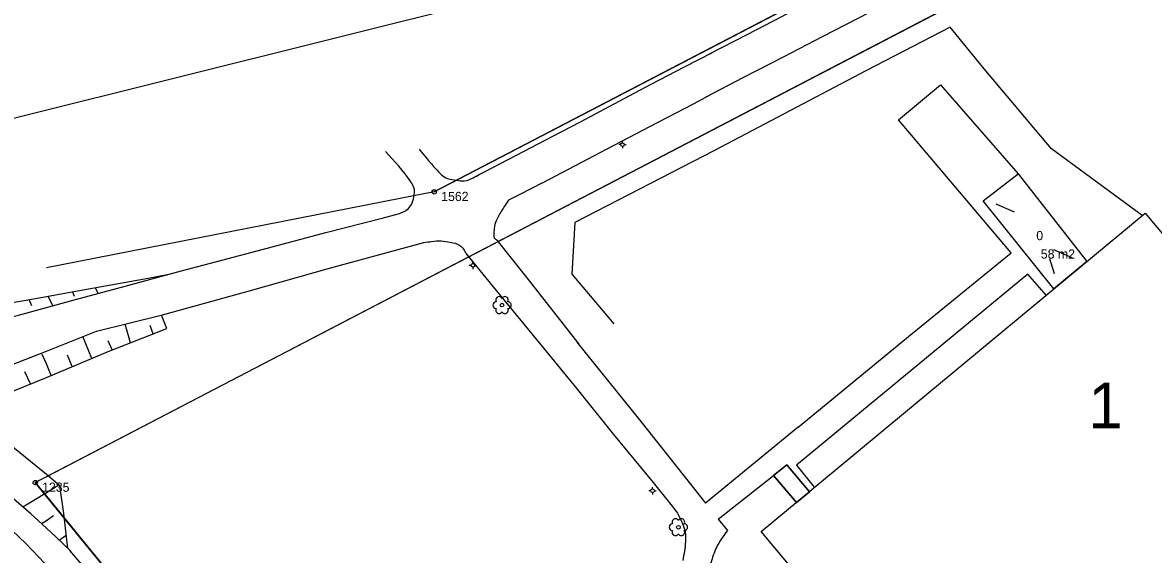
# Model space of a CAD drawing. Extents: x 1517478 to 1518189, y 6494860 to 6495389.
# Drawn here: x 1517715.6 to 1517838.6, y 6495049.6 to 6495107.4 of the extents above; entities that cross this region are included whole.
import ezdxf

# ---------------------------------------------------------------- set-up
doc = ezdxf.new("R2010")
doc.units = 0
for name, color, linetype in [('allmanbygg_symbollinje', 7, 'Continuous'), ('allmanbyggnad', 7, 'Continuous'), ('allmanbyggnad_nummer', 7, 'Continuous'), ('byggnad_areatext', 7, 'Continuous'), ('fastighetsbeteckning', 7, 'Continuous'), ('gc_vag', 7, 'Continuous'), ('grans', 7, 'Continuous'), ('granspunkt', 7, 'Continuous'), ('granspunkt_text', 7, 'Continuous'), ('kvartersgrans', 7, 'Continuous'), ('kvartersytor', 7, 'Continuous'), ('ledningar', 7, 'Continuous'), ('lovtrad', 7, 'Continuous'), ('slant_skraffering', 7, 'Continuous'), ('slantfot', 7, 'Continuous'), ('slantkron', 7, 'Continuous'), ('staket', 7, 'Continuous'), ('stolpe_belysning', 7, 'Continuous'), ('uthus', 7, 'Continuous'), ('uthus_yta', 7, 'Continuous')]:
    doc.layers.add(name, color=color, linetype=linetype)

msp = doc.modelspace()

# ---------------------------------------------------------------- linework, layer by layer
at = {"layer": 'allmanbygg_symbollinje'}
for p, q in [((1517821.5, 6495087.7), (1517823.5, 6495086.83)), ((1517827.76, 6495082.74), (1517829.76, 6495081.87)), ((1517827.33, 6495081.78), (1517827.85, 6495080.13))]:
    msp.add_line(p, q, dxfattribs=at)
at = {"layer": 'allmanbyggnad'}
for points in [[(1517827.79, 6495078.45), (1517820.11, 6495088.05), (1517823.93, 6495091), (1517831.39, 6495081.44), (1517827.79, 6495078.45)], [(1517795.98, 6495052.03), (1517837.72, 6495086.69), (1517844.24, 6495078.9), (1517844.89, 6495079.4), (1517856.96, 6495064.93), (1517856.28, 6495064.33), (1517862.19, 6495057.11), (1517842.98, 6495041.23), (1517844.57, 6495039.29), (1517839.38, 6495035.07), (1517847.33, 6495025.71), (1517853.22, 6495030.6), (1517862.35, 6495019.75), (1517850.98, 6495010.13), (1517853.38, 6495007.24), (1517840.06, 6494996.19), (1517822.37, 6495017.44), (1517823.84, 6495018.69), (1517795.97, 6495052.03)]]:
    msp.add_lwpolyline(points, dxfattribs=at)
at = {"layer": 'gc_vag'}
for p, q in [((1517799.97, 6495063.4), (1517789.92, 6495055.14)), ((1517791.3, 6495053.39), (1517797.31, 6495058.14))]:
    msp.add_line(p, q, dxfattribs=at)
for points in [[(1517790.33, 6495104.03), (1517794.43, 6495106.16), (1517798.2, 6495108.12), (1517802.73, 6495110.59), (1517806.54, 6495112.54), (1517810.49, 6495114.65), (1517815.16, 6495117.15)], [(1517789.99, 6495099.37), (1517794, 6495101.48), (1517798.46, 6495103.77), (1517802.62, 6495105.94), (1517809.04, 6495109.25), (1517812.59, 6495111.02), (1517815.82, 6495112.87)], [(1517764.88, 6495090.69), (1517769.35, 6495093.03), (1517773.3, 6495095.1), (1517776.31, 6495096.66), (1517781.06, 6495099.2), (1517783.99, 6495100.76), (1517787.62, 6495102.64), (1517790.66, 6495104.2)], [(1517772.17, 6495090.02), (1517779.21, 6495093.72), (1517783.85, 6495096.12), (1517788.59, 6495098.62), (1517790.41, 6495099.6)], [(1517799.97, 6495063.4), (1517812.39, 6495073.6), (1517823.16, 6495082.38), (1517810.9, 6495096.88), (1517815.46, 6495100.69), (1517823.93, 6495091)], [(1517772.17, 6495090.02), (1517769.71, 6495088.75), (1517768.49, 6495088.13)], [(1517741.82, 6495082.79), (1517748.6, 6495084.6), (1517754.72, 6495086.16), (1517756.63, 6495086.67)], [(1517767.22, 6495083.77), (1517770.63, 6495079.47), (1517776.14, 6495072.45)], [(1517718.21, 6495076.42), (1517720.99, 6495077.19), (1517726.79, 6495078.74), (1517732.75, 6495080.4), (1517741.82, 6495082.79)], [(1517740.16, 6495078.22), (1517749.02, 6495080.71), (1517759.28, 6495083.51)], [(1517763.9, 6495082.25), (1517767.15, 6495078.3), (1517772, 6495072.37)], [(1517826.96, 6495077.76), (1517824.98, 6495080.06), (1517799.8, 6495059.26), (1517801.71, 6495056.86), (1517801.74, 6495056.82)], [(1517718.21, 6495071.68), (1517721.14, 6495072.83), (1517723.68, 6495073.87), (1517730.83, 6495075.63), (1517740.16, 6495078.22)], [(1517700.61, 6495070.56), (1517703.99, 6495071.93), (1517708.29, 6495073.5), (1517711.55, 6495074.7), (1517715.18, 6495075.58), (1517718.21, 6495076.42)], [(1517775.91, 6495072.65), (1517782.88, 6495064.02), (1517788.43, 6495057)], [(1517704.19, 6495066.15), (1517707.86, 6495067.56), (1517713.58, 6495069.88), (1517718.21, 6495071.68)], [(1517772, 6495072.37), (1517775.96, 6495067.55), (1517779.9, 6495062.62), (1517784.2, 6495057.38)], [(1517718.21, 6495048.34), (1517718.04, 6495048.55), (1517715.97, 6495050.73), (1517714.5, 6495052.16), (1517712.54, 6495053.95), (1517710.97, 6495055.35), (1517708.65, 6495057.17), (1517706.66, 6495058.85), (1517705.01, 6495060.19), (1517703.14, 6495061.88)], [(1517718.21, 6495052.42), (1517716.53, 6495053.98), (1517714.43, 6495055.8), (1517712.37, 6495057.63), (1517709.95, 6495059.83), (1517708.09, 6495061.41), (1517707.3, 6495062.11)], [(1517784.2, 6495057.38), (1517786.12, 6495054.97), (1517786.77, 6495054.17)], [(1517788.43, 6495057), (1517789.92, 6495055.14)], [(1517791.3, 6495053.39), (1517792.29, 6495052.15)], [(1517720.91, 6495049.85), (1517719.2, 6495051.5), (1517718.21, 6495052.42)], [(1517724.81, 6495044.99), (1517723.5, 6495046.63), (1517721.86, 6495048.69), (1517720.78, 6495049.96)]]:
    msp.add_lwpolyline(points, dxfattribs=at)
for points in [[(1517756.63, 6495086.67), (1517757.47, 6495087.09), (1517757.93, 6495087.65), (1517758.19, 6495088.44), (1517758.19, 6495089.49), (1517757.85, 6495090.13), (1517755.1, 6495093.4)], [(1517758.77, 6495093.66), (1517760.56, 6495091.53), (1517761.86, 6495090.48), (1517762.8, 6495090.3), (1517763.67, 6495090.22), (1517764.62, 6495090.55), (1517765.34, 6495090.95)], [(1517768.49, 6495088.13), (1517767.89, 6495087.22), (1517767.24, 6495086.08), (1517766.96, 6495085.25), (1517766.88, 6495084.42), (1517766.93, 6495084), (1517767.22, 6495083.77)], [(1517759.28, 6495083.51), (1517760.12, 6495083.62), (1517761.16, 6495083.69), (1517762.11, 6495083.54), (1517762.84, 6495083.36), (1517763.31, 6495083.1), (1517763.95, 6495082.16)], [(1517786.77, 6495054.17), (1517787.37, 6495053), (1517787.7, 6495051.97), (1517787.73, 6495050.93), (1517787.44, 6495048.88)], [(1517792.29, 6495052.15), (1517791.1, 6495050.31), (1517790.48, 6495048.62), (1517790.09, 6495047.12), (1517789.98, 6495045.77), (1517790.03, 6495044.42)]]:
    msp.add_spline(points, degree=3, dxfattribs=at)
at = {"layer": 'grans'}
for p, q in [((1517760.41, 6495089.02), (1517815.51, 6495117.75)), ((1517819.97, 6495111.05), (1517718.21, 6495058)), ((1517760.41, 6495089.02), (1517718.21, 6495080.76)), ((1517718.21, 6495058), (1517717, 6495057.37)), ((1517717, 6495057.37), (1517718.21, 6495055.89)), ((1517718.21, 6495055.89), (1517772.4, 6494989.39))]:
    msp.add_line(p, q, dxfattribs=at)
at = {"layer": 'granspunkt'}
for centre in [(1517760.41, 6495089.02), (1517717, 6495057.37)]:
    msp.add_circle(centre, 0.237, dxfattribs=at)
at = {"layer": 'kvartersgrans'}
for p, q in [((1517819.97, 6495111.05), (1517718.21, 6495058)), ((1517760.41, 6495089.02), (1517718.21, 6495080.76))]:
    msp.add_line(p, q, dxfattribs=at)
for points in [[(1517915.64, 6495201.43), (1517827.1, 6495127.44), (1517815.51, 6495117.75), (1517760.41, 6495089.02)], [(1517718.21, 6495058), (1517717, 6495057.37), (1517718.21, 6495055.89)], [(1517718.21, 6495055.89), (1517772.4, 6494989.39), (1517780.49, 6494980.71), (1517789.65, 6494973.16), (1517799.72, 6494966.88)]]:
    msp.add_lwpolyline(points, dxfattribs=at)
at = {"layer": 'kvartersytor'}
msp.add_lwpolyline([(1517845.48, 6494956.3), (1517833.61, 6494956.65), (1517821.9, 6494958.56), (1517816.22, 6494960.27), (1517810.53, 6494961.99), (1517807.17, 6494963.51), (1517799.72, 6494966.88), (1517794.69, 6494970.02), (1517789.65, 6494973.16), (1517785.07, 6494976.93), (1517780.49, 6494980.71), (1517776.44, 6494985.05), (1517772.4, 6494989.39), (1517745.3, 6495022.64), (1517717, 6495057.37), (1517819.97, 6495111.05)], dxfattribs=at)
at = {"layer": 'ledningar'}
msp.add_lwpolyline([(1517680.89, 6495088.62), (1517783.53, 6495114.28), (1517923.32, 6495228.43), (1517982.59, 6495318.69)], dxfattribs=at)
at = {"layer": 'lovtrad'}
for centre in [(1517767.77, 6495076.69), (1517786.96, 6495052.51)]:
    msp.add_circle(centre, 0.2, dxfattribs=at)
for centre, start, end in [((1517767.46, 6495077.25), 29.1347, 212.3057), ((1517768.09, 6495077.25), 329.1331, 150.8613), ((1517767.14, 6495076.69), 89.5389, 268.9887), ((1517767.46, 6495076.14), 150.5831, 330.865), ((1517768.09, 6495076.14), 209.1844, 30.8583), ((1517768.41, 6495076.69), 269.1508, 90.8733), ((1517786.33, 6495052.5), 89.5389, 268.9887), ((1517786.64, 6495053.07), 29.1347, 212.3057), ((1517787.28, 6495053.07), 329.1331, 150.8613), ((1517787.6, 6495052.51), 269.1508, 90.8733), ((1517786.64, 6495051.96), 150.5831, 330.865), ((1517787.28, 6495051.96), 209.1844, 30.8583)]:
    msp.add_arc(centre, 0.366, start, end, dxfattribs=at)
at = {"layer": 'slant_skraffering'}
for p, q in [((1517718.38, 6495077.65), (1517718.9, 6495076.61)), ((1517721.04, 6495078.13), (1517721.25, 6495077.67)), ((1517723.51, 6495078.58), (1517723.84, 6495077.95)), ((1517716.34, 6495077.28), (1517716.61, 6495076.65)), ((1517727.36, 6495072.59), (1517726.77, 6495074.63)), ((1517729.82, 6495073.55), (1517729.51, 6495074.46)), ((1517723.14, 6495070.89), (1517722.19, 6495073.26)), ((1517725.37, 6495071.81), (1517724.94, 6495072.82)), ((1517718.74, 6495069.04), (1517718.21, 6495070.3)), ((1517721.02, 6495070), (1517720.5, 6495071.25)), ((1517716.5, 6495068.12), (1517715.86, 6495069.41)), ((1517718.21, 6495056.29), (1517719.58, 6495057.12)), ((1517715.66, 6495054.74), (1517718.21, 6495056.29)), ((1517717.68, 6495052.91), (1517718.21, 6495053.26)), ((1517718.21, 6495053.26), (1517719, 6495053.78)), ((1517719.61, 6495051.1), (1517720.38, 6495051.64))]:
    msp.add_line(p, q, dxfattribs=at)
msp.add_lwpolyline([(1517718.21, 6495070.3), (1517717.77, 6495071.32), (1517717.78, 6495071.25), (1517717.78, 6495071.25)], dxfattribs=at)
at = {"layer": 'slantfot'}
for points in [[(1517718.21, 6495058.24), (1517709.5, 6495065.32), (1517708.29, 6495065.42)], [(1517720.54, 6495050.21), (1517720.11, 6495054.02), (1517719.69, 6495057.03), (1517718.21, 6495058.24)]]:
    msp.add_lwpolyline(points, dxfattribs=at)
at = {"layer": 'slantkron'}
for points in [[(1517718.21, 6495077.62), (1517722.38, 6495078.38), (1517729.28, 6495079.62), (1517731.34, 6495080.01)], [(1517703.11, 6495074.93), (1517709.27, 6495076.1), (1517715.8, 6495077.19), (1517718.21, 6495077.62)], [(1517718.21, 6495068.81), (1517724.92, 6495071.64), (1517731.3, 6495074.13), (1517730.74, 6495075.61)], [(1517709.52, 6495065.3), (1517718.03, 6495068.74), (1517718.21, 6495068.81)]]:
    msp.add_lwpolyline(points, dxfattribs=at)
at = {"layer": 'staket'}
msp.add_line((1517837.41, 6495086.43), (1517827.55, 6495093.72), dxfattribs=at)
for points in [[(1517827.55, 6495093.72), (1517820.39, 6495102.2), (1517816.53, 6495106.95), (1517807.35, 6495102.2), (1517790.87, 6495093.51)], [(1517790.87, 6495093.51), (1517775.7, 6495085.69), (1517775.37, 6495080.06), (1517779.93, 6495074.67)]]:
    msp.add_lwpolyline(points, dxfattribs=at)
at = {"layer": 'stolpe_belysning'}
for p, q in [((1517780.67, 6495094.16), (1517780.47, 6495094.16)), ((1517780.87, 6495094.36), (1517780.87, 6495094.56)), ((1517780.87, 6495093.96), (1517780.87, 6495093.76)), ((1517781.07, 6495094.16), (1517781.27, 6495094.16)), ((1517764.61, 6495081.22), (1517764.61, 6495081.42)), ((1517764.41, 6495081.02), (1517764.21, 6495081.02)), ((1517764.61, 6495080.82), (1517764.61, 6495080.62)), ((1517764.81, 6495081.02), (1517765.01, 6495081.02)), ((1517784.15, 6495056.68), (1517784.15, 6495056.88)), ((1517783.95, 6495056.48), (1517783.75, 6495056.48)), ((1517784.15, 6495056.28), (1517784.15, 6495056.08)), ((1517784.35, 6495056.48), (1517784.55, 6495056.48))]:
    msp.add_line(p, q, dxfattribs=at)
for centre in [(1517780.87, 6495094.16), (1517764.61, 6495081.02), (1517784.15, 6495056.48)]:
    msp.add_circle(centre, 0.2, dxfattribs=at)
at = {"layer": 'uthus'}
msp.add_lwpolyline([(1517801.21, 6495056.38), (1517798.77, 6495059.31), (1517797.31, 6495058.14), (1517799.79, 6495055.2), (1517801.21, 6495056.38)], dxfattribs=at)
at = {"layer": 'uthus_yta'}
msp.add_lwpolyline([(1517799.79, 6495055.2), (1517797.31, 6495058.14), (1517798.77, 6495059.31), (1517801.21, 6495056.38)], close=True, dxfattribs=at)

# ---------------------------------------------------------------- texts
at = {"layer": 'allmanbyggnad_nummer'}
msp.add_text('0', height=1, dxfattribs=at).set_placement((1517825.89, 6495083.76))
at = {"layer": 'byggnad_areatext'}
msp.add_text('58 m2', height=1, dxfattribs=at).set_placement((1517826.38, 6495081.76))
at = {"layer": 'fastighetsbeteckning'}
msp.add_text('1', height=5, rotation=0.0021, dxfattribs=at).set_placement((1517831.56, 6495063.26))
at = {"layer": 'granspunkt_text'}
for s, p in [('1562', (1517761.16, 6495088.02)), ('1235', (1517717.75, 6495056.37))]:
    msp.add_text(s, height=1, dxfattribs=at).set_placement(p)

doc.saveas('drawing.dxf')
